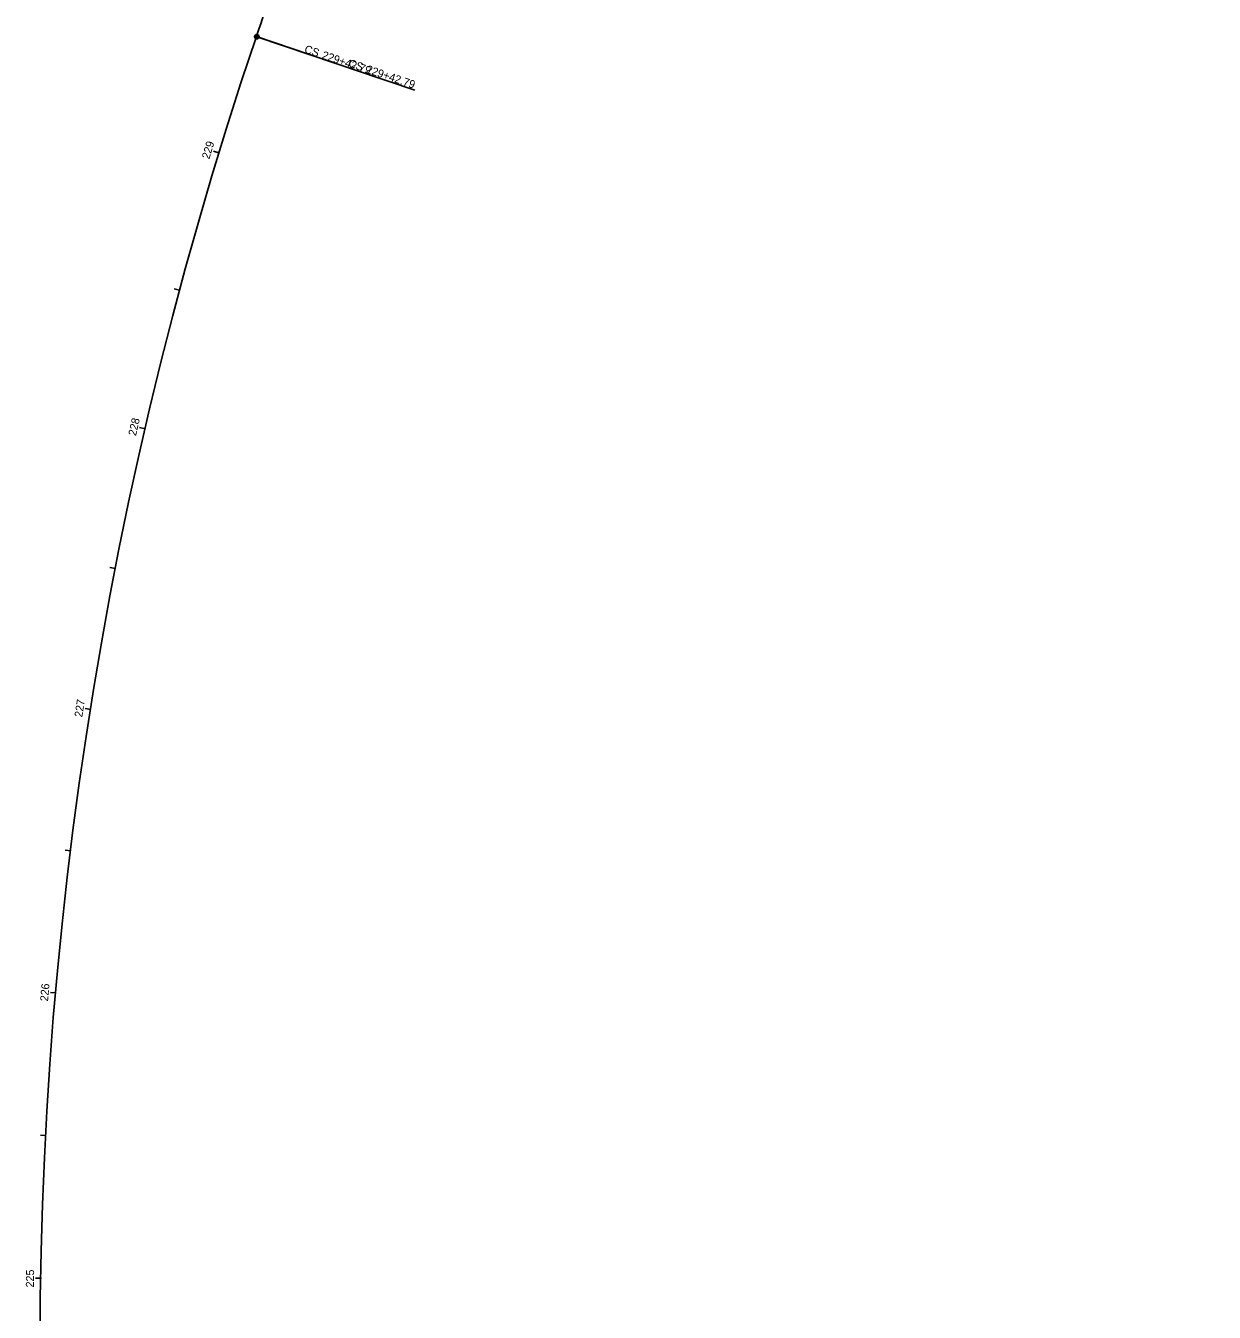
# Model space of a CAD drawing. Extents: x 1454426 to 1455277, y 587472 to 590476.
# Drawn here: x 1454425.8 to 1454841.7, y 588782.9 to 589233.1 of the extents above; entities that cross this region are included whole.
import ezdxf

# ---------------------------------------------------------------- set-up
doc = ezdxf.new("R2010")
doc.units = 0
for name, color, linetype in [('Default', 7, 'Continuous'), ('GT_Target_Soil_Boring', 7, 'Continuous'), ('PV_P_Saw_Cut_Line', 7, 'Continuous'), ('SC_Scratch1', 7, 'Continuous'), ('SC_Scratch2', 7, 'Continuous'), ('SC_Scratch3', 7, 'Continuous')]:
    doc.layers.add(name, color=color, linetype=linetype)

msp = doc.modelspace()

# ---------------------------------------------------------------- linework, layer by layer
at = {"layer": 'Default'}
for centre in [(1454506.47, 589229.34), (1454506.47, 589229.34), (1454506.47, 589229.34), (1454493.37, 589188.61), (1454493.37, 589188.61), (1454493.37, 589188.61), (1454467.54, 589092.02), (1454467.54, 589092.02), (1454467.54, 589092.02), (1454448.52, 588993.87), (1454448.52, 588993.87), (1454448.52, 588993.87), (1454436.38, 588894.63), (1454436.38, 588894.63), (1454436.38, 588894.63), (1454431.2, 588794.78), (1454431.2, 588794.78), (1454431.2, 588794.78)]:
    msp.add_circle(centre, 0.0000833, dxfattribs=at)
at = {"layer": 'GT_Target_Soil_Boring'}
msp.add_arc((1455863.38, 588770.51), 1432.39, 161.3175, 244.97965, dxfattribs=at)
msp.add_open_spline([(1454506.47, 589229.34), (1454509.14, 589237.23), (1454514.62, 589252.97), (1454526.1, 589284.27), (1454541.33, 589323.06), (1454560.83, 589369.1), (1454581.33, 589414.71), (1454602.61, 589459.95), (1454624.49, 589504.92), (1454643.05, 589542.22), (1454657.99, 589572.02), (1454665.48, 589586.91), (1454669.23, 589594.35)], degree=3, dxfattribs=at)
at = {"layer": 'PV_P_Saw_Cut_Line'}
msp.add_arc((1455863.38, 588770.51), 1432.39, 161.3175, 244.97965, dxfattribs=at)
at = {"layer": 'SC_Scratch1'}
for p, q in [((1454506.64, 589229.28), (1454561.93, 589210.57)), ((1454493.37, 589188.61), (1454491.46, 589189.19)), ((1454479.61, 589140.54), (1454477.68, 589141.06)), ((1454467.54, 589092.02), (1454465.59, 589092.47)), ((1454457.17, 589043.11), (1454455.21, 589043.49)), ((1454448.52, 588993.87), (1454446.54, 588994.18)), ((1454441.58, 588944.36), (1454439.6, 588944.6)), ((1454436.38, 588894.63), (1454434.39, 588894.8)), ((1454432.92, 588844.75), (1454430.92, 588844.86)), ((1454431.2, 588794.78), (1454429.2, 588794.82))]:
    msp.add_line(p, q, dxfattribs=at)
msp.add_circle((1454506.64, 589229.28), 0.778, dxfattribs=at)
at = {"layer": 'SC_Scratch2'}
for p, q in [((1454506.47, 589229.34), (1454549.09, 589214.91)), ((1454493.37, 589188.61), (1454491.46, 589189.19)), ((1454479.61, 589140.54), (1454477.68, 589141.06)), ((1454467.54, 589092.02), (1454465.59, 589092.47)), ((1454457.17, 589043.11), (1454455.21, 589043.49)), ((1454448.52, 588993.87), (1454446.54, 588994.18)), ((1454441.58, 588944.36), (1454439.6, 588944.6)), ((1454436.38, 588894.63), (1454434.39, 588894.8)), ((1454432.92, 588844.75), (1454430.92, 588844.86)), ((1454431.2, 588794.78), (1454429.2, 588794.82))]:
    msp.add_line(p, q, dxfattribs=at)
msp.add_circle((1454506.47, 589229.34), 0.6, dxfattribs=at)
at = {"layer": 'SC_Scratch3'}
for p, q in [((1454506.47, 589229.34), (1454549.09, 589214.91)), ((1454493.37, 589188.61), (1454491.46, 589189.19)), ((1454479.61, 589140.54), (1454477.68, 589141.06)), ((1454467.54, 589092.02), (1454465.59, 589092.47)), ((1454457.17, 589043.11), (1454455.21, 589043.49)), ((1454448.52, 588993.87), (1454446.54, 588994.18)), ((1454441.58, 588944.36), (1454439.6, 588944.6)), ((1454436.38, 588894.63), (1454434.39, 588894.8)), ((1454432.92, 588844.75), (1454430.92, 588844.86)), ((1454431.2, 588794.78), (1454429.2, 588794.82))]:
    msp.add_line(p, q, dxfattribs=at)
msp.add_circle((1454506.47, 589229.34), 0.6, dxfattribs=at)

# ---------------------------------------------------------------- texts
at = {"layer": 'SC_Scratch1'}
for s, rotation, p in [('CS', 341.302, (1454538.43, 589218.85)), ('229+42.79', 341.302, (1454544.61, 589216.75)), ('229', 73.029, (1454489.99, 589186.24)), ('228', 77.029, (1454464.33, 589089.4)), ('227', 81.029, (1454445.53, 588990.96)), ('226', 85.029, (1454433.56, 588891.58)), ('225', 89.029, (1454428.6, 588791.53))]:
    msp.add_text(s, height=2.8, rotation=rotation, dxfattribs=at).set_placement(p)
at = {"layer": 'SC_Scratch2'}
for s, rotation, p in [('CS', 341.302, (1454523.02, 589223.79)), ('229+42.79', 341.302, (1454529.19, 589221.7)), ('229', 73.029, (1454489.99, 589186.24)), ('228', 77.029, (1454464.33, 589089.4)), ('227', 81.029, (1454445.53, 588990.96)), ('226', 85.029, (1454433.56, 588891.58)), ('225', 89.029, (1454428.6, 588791.53))]:
    msp.add_text(s, height=2.8, rotation=rotation, dxfattribs=at).set_placement(p)
at = {"layer": 'SC_Scratch3'}
for s, rotation, p in [('CS', 341.302, (1454523.02, 589223.79)), ('229+42.79', 341.302, (1454529.19, 589221.7)), ('229', 73.029, (1454489.99, 589186.24)), ('228', 77.029, (1454464.33, 589089.4)), ('227', 81.029, (1454445.53, 588990.96)), ('226', 85.029, (1454433.56, 588891.58)), ('225', 89.029, (1454428.6, 588791.53))]:
    msp.add_text(s, height=2.8, rotation=rotation, dxfattribs=at).set_placement(p)

doc.saveas('drawing.dxf')
